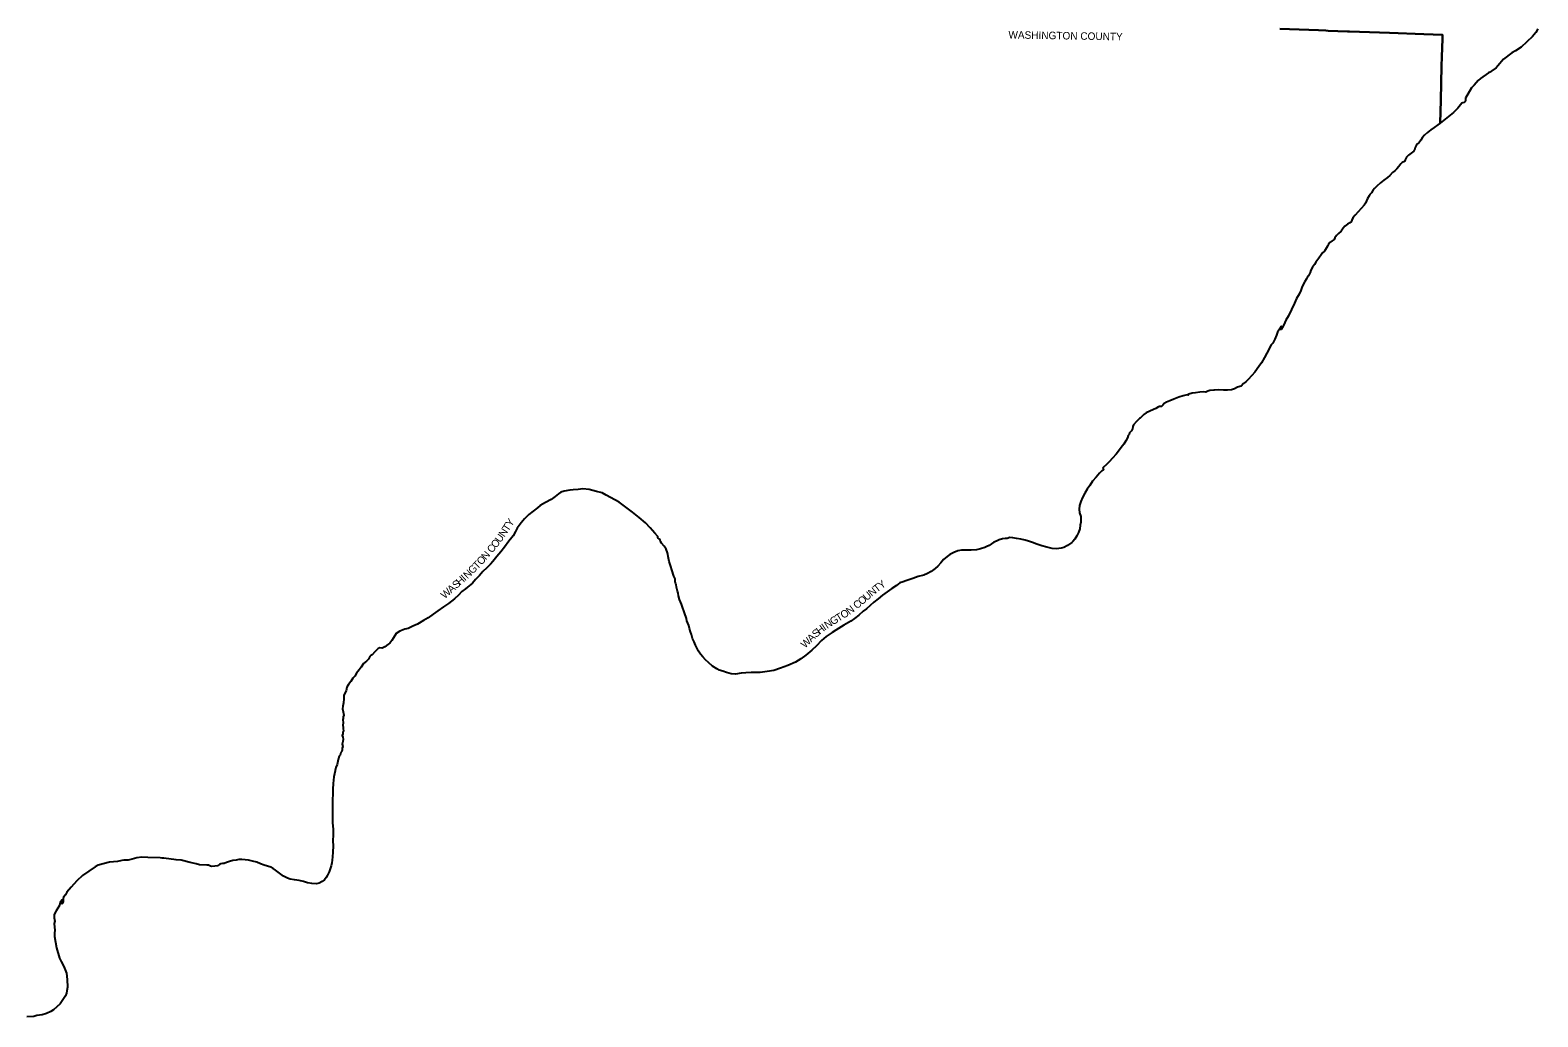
# Model space of a CAD drawing. Extents: x 2043100 to 2470832, y 443715 to 810583.
# Drawn here: x 2192662 to 2393554, y 445118 to 576519 of the extents above; entities that cross this region are included whole.
import ezdxf

# ---------------------------------------------------------------- set-up
doc = ezdxf.new("R2010")
doc.units = 0
doc.layers.add('GM_X_Adjacent_County', color=7, linetype='Continuous')
doc.layers.add('GM_X_Adjacent_County_Text', color=7, linetype='Continuous')

msp = doc.modelspace()

# ---------------------------------------------------------------- linework, layer by layer
at = {"layer": 'GM_X_Adjacent_County'}
for points in [[(2359185, 576678), (2364316, 576498), (2365308, 576463), (2365624, 576452), (2368204, 576361), (2368448, 576353), (2373769, 576167), (2378345, 576006), (2380854, 575918), (2380838, 575354), (2380769, 572951), (2380735, 571740), (2380605, 567204), (2380518, 564153), (2380206, 563892), (2379758, 563556), (2379288, 563234), (2378848, 562883), (2378470, 562536), (2378155, 562185), (2377945, 561869), (2377755, 561577), (2377505, 561385), (2377336, 561168), (2377212, 560895), (2377115, 560525), (2377027, 560393), (2376654, 560121), (2376323, 559858), (2376068, 559619), (2375885, 559250), (2375782, 559024), (2375479, 558909), (2375289, 558727), (2375028, 558347), (2374766, 558062), (2374493, 557793), (2374165, 557570), (2373843, 557168), (2373530, 556895), (2373042, 556563), (2372604, 556201), (2372102, 555735), (2371767, 555419), (2371585, 555176), (2371371, 554852), (2371178, 554644), (2371088, 554460), (2370837, 554120), (2370569, 553501), (2370393, 553211), (2369999, 552760), (2369610, 552327), (2369210, 551890), (2368917, 551519), (2368761, 551212), (2368686, 550992), (2368522, 550842), (2368192, 550662), (2367843, 550404), (2367622, 550168), (2367327, 549761), (2366995, 549445), (2366741, 549162), (2366506, 548866), (2366395, 548652), (2366135, 548480), (2365854, 548249), (2365642, 548032), (2365536, 547748), (2365134, 547107), (2364877, 546854), (2364696, 546593), (2364360, 546141), (2363968, 545629), (2363804, 545330), (2363535, 544941), (2363322, 544577), (2363228, 544253), (2363123, 544059), (2363006, 543787), (2362807, 543586), (2362717, 543406), (2362498, 543056), (2362146, 542376), (2361975, 541860), (2361734, 541352), (2361415, 540780), (2361115, 540184), (2360315, 538483), (2359971, 537881), (2359689, 537272), (2359486, 536874), (2359335, 536647), (2359273, 536653), (2359306, 536837), (2359382, 537043), (2359347, 537046), (2359208, 536848), (2358867, 536280), (2358724, 535921), (2358497, 535373), (2358222, 534848), (2358019, 534604), (2357455, 533512), (2357145, 532912), (2356738, 532231), (2356377, 531721), (2355846, 530970), (2355433, 530532), (2354970, 530004), (2354659, 529665), (2354350, 529463), (2354041, 529120), (2353556, 528965), (2353151, 528748), (2352753, 528626), (2352208, 528569), (2351661, 528569), (2350972, 528598), (2350479, 528585), (2350400, 528583), (2349862, 528548), (2349583, 528421), (2349313, 528313), (2348975, 528369), (2348537, 528331), (2347940, 528220), (2347503, 528156), (2347041, 528032), (2346952, 527931), (2346811, 527945), (2346309, 527818), (2345704, 527644), (2345063, 527390), (2344527, 527134), (2344075, 526994), (2343750, 526810), (2343566, 526563), (2343397, 526414), (2343163, 526415), (2342991, 526351), (2342666, 526142), (2342340, 525992), (2341853, 525795), (2341351, 525570), (2341049, 525346), (2340734, 525003), (2340546, 524863), (2340463, 524801), (2340068, 524423), (2339684, 523960), (2339602, 523729), (2339555, 523445), (2339408, 523168), (2339147, 522882), (2339085, 522675), (2338980, 522553), (2338875, 522239), (2338667, 521831), (2338370, 521374), (2338022, 520920), (2337680, 520450), (2337345, 520055), (2336894, 519540), (2336444, 519041), (2336061, 518661), (2335630, 518270), (2335611, 518186), (2335668, 518090), (2335642, 517973), (2335459, 517843), (2335167, 517536), (2334720, 516997), (2334233, 516435), (2333838, 515901), (2333500, 515393), (2333210, 514860), (2332875, 514302), (2332647, 513749), (2332473, 513195), (2332429, 512723), (2332495, 512255), (2332638, 511741), (2332655, 510988), (2332590, 510576), (2332541, 510102), (2332358, 509624), (2332127, 509182), (2331841, 508713), (2331602, 508406), (2331455, 508309), (2330863, 507893), (2330384, 507638), (2330030, 507541), (2329425, 507441), (2328832, 507500), (2328123, 507666), (2327474, 507837), (2326813, 508075), (2326238, 508285), (2325695, 508473), (2325222, 508593), (2324670, 508715), (2324100, 508826), (2323589, 508916), (2323215, 508939), (2322845, 508833), (2322572, 508841), (2322229, 508775), (2321769, 508622), (2321440, 508478), (2321065, 508329), (2320764, 508110), (2320444, 507909), (2320135, 507772), (2319874, 507626), (2319311, 507457), (2318746, 507330), (2318043, 507272), (2317315, 507264), (2316756, 507274), (2316268, 507188), (2315742, 506970), (2315218, 506698), (2314827, 506431), (2314358, 506010), (2313985, 505587), (2313600, 505142), (2313254, 504843), (2312699, 504415), (2312237, 504148), (2311723, 503952), (2310978, 503755), (2310274, 503508), (2309330, 503196), (2308967, 503072), (2308524, 502898), (2308078, 502547), (2307489, 502168), (2306856, 501732), (2306237, 501272), (2305654, 500793), (2305073, 500323), (2304576, 499879), (2304111, 499448), (2303675, 499131), (2303064, 498607), (2302491, 498180), (2301995, 497820), (2301376, 497477), (2301082, 497264), (2300722, 497072), (2300023, 496611), (2299524, 496324), (2298725, 495767), (2298099, 495219), (2297431, 494533), (2296800, 493953), (2296025, 493278), (2295345, 492775), (2294655, 492372), (2293617, 491910), (2292655, 491546), (2291769, 491263), (2290855, 491114), (2289954, 490997), (2289559, 490973), (2289341, 490960), (2288715, 490966), (2288016, 490944), (2287383, 490875), (2286660, 490773), (2286056, 490817), (2285464, 490960), (2284954, 491136), (2284481, 491291), (2284164, 491450), (2283576, 491824), (2283033, 492289), (2282659, 492669), (2282308, 493064), (2282001, 493427), (2281709, 493831), (2281489, 494244), (2281297, 494604), (2281121, 495045), (2280921, 495490), (2280783, 496014), (2280636, 496385), (2280536, 496855), (2280445, 497253), (2280298, 497542), (2280170, 497855), (2280120, 498186), (2280048, 498454), (2279925, 498667), (2279466, 500083), (2279204, 500711), (2279052, 501183), (2278991, 501521), (2278930, 501793), (2278781, 502329), (2278744, 502688), (2278661, 502876), (2278586, 503111), (2278615, 503433), (2278431, 503803), (2278369, 503938), (2278186, 504513), (2277983, 505206), (2277802, 505761), (2277702, 506219), (2277589, 506900), (2277426, 507395), (2277151, 507806), (2276777, 508205), (2276649, 508405), (2276618, 508581), (2276529, 508718), (2276309, 508901), (2276280, 509075), (2275910, 509542), (2275255, 510256), (2274636, 510903), (2273828, 511604), (2272919, 512325), (2272197, 512856), (2271126, 513670), (2270589, 513992), (2269398, 514614), (2268891, 514898), (2268137, 515102), (2267168, 515352), (2266312, 515423), (2265671, 515365), (2265009, 515320), (2264563, 515262), (2263811, 515125), (2263356, 514994), (2263070, 514786), (2262636, 514413), (2262095, 514016), (2261334, 513617), (2260616, 513223), (2260245, 512907), (2259694, 512482), (2259107, 512000), (2258521, 511447), (2258074, 510887), (2257566, 510198), (2257338, 509734), (2257013, 509158), (2256854, 508971), (2256429, 508462), (2255864, 507670), (2255387, 507057), (2254857, 506411), (2254319, 505772), (2253982, 505392), (2253507, 504928), (2253001, 504419), (2252542, 503905), (2252006, 503353), (2251583, 502884), (2251177, 502528), (2250955, 502356), (2250684, 502138), (2250188, 501741), (2249741, 501262), (2249195, 500794), (2248393, 500170), (2247748, 499699), (2246994, 499182), (2246371, 498723), (2245716, 498276), (2245080, 497887), (2244288, 497429), (2243667, 497133), (2243040, 496830), (2242588, 496730), (2241930, 496473), (2241433, 496184), (2241096, 495614), (2240859, 495254), (2240569, 494878), (2240337, 494684), (2239912, 494384), (2239556, 494195), (2239243, 494275), (2239039, 494178), (2238608, 493740), (2238229, 493334), (2238064, 493258), (2237908, 493090), (2237742, 492737), (2237477, 492483), (2237076, 492185), (2236746, 491696), (2236496, 491330), (2236139, 490896), (2235908, 490496), (2235666, 490202), (2235373, 489758), (2235077, 489371), (2234872, 489002), (2234776, 488541), (2234599, 488234), (2234451, 487906), (2234460, 487477), (2234409, 486927), (2234316, 486487), (2234292, 486124), (2234360, 485720), (2234442, 485282), (2234378, 485063), (2234375, 484846), (2234303, 484701), (2234363, 484251), (2234340, 483978), (2234376, 483668), (2234349, 483453), (2234400, 483225), (2234338, 483046), (2234345, 482828), (2234258, 482570), (2234303, 482346), (2234375, 482112), (2234314, 481805), (2234255, 481449), (2234319, 481134), (2234258, 480908), (2234243, 480690), (2234174, 480450), (2234079, 480299), (2233964, 479955), (2233853, 479821), (2233711, 479382), (2233559, 478729), (2233394, 478316), (2233305, 477906), (2233295, 477864), (2233143, 477090), (2233029, 476171), (2232988, 475460), (2232976, 474703), (2232945, 474139), (2232932, 473117), (2232928, 471946), (2232956, 471018), (2233026, 470053), (2233049, 469368), (2233004, 468537), (2233031, 467894), (2232992, 467062), (2232964, 466440), (2232924, 465981), (2232848, 465645), (2232757, 465239), (2232618, 464850), (2232496, 464420), (2232277, 463974), (2232115, 463663), (2231898, 463370), (2231549, 463121), (2231193, 462926), (2230828, 462831), (2230216, 462871), (2229628, 462984), (2229095, 463122), (2228506, 463294), (2227875, 463385), (2227313, 463474), (2226945, 463579), (2226400, 463853), (2226069, 464105), (2225716, 464381), (2225344, 464629), (2225021, 464861), (2224744, 465036), (2224291, 465175), (2223855, 465303), (2223369, 465513), (2222868, 465697), (2222273, 465870), (2221748, 465982), (2221299, 466030), (2220876, 466054), (2220473, 466057), (2220111, 466004), (2219669, 465921), (2219222, 465801), (2218821, 465659), (2218496, 465551), (2218276, 465534), (2218050, 465509), (2217889, 465418), (2217626, 465249), (2217285, 465168), (2216888, 465155), (2216673, 465184), (2216430, 465295), (2216198, 465304), (2215240, 465376), (2214796, 465508), (2213975, 465680), (2212780, 465966), (2212123, 466022), (2210454, 466256), (2210241, 466256), (2209964, 466298), (2208339, 466328), (2207555, 466366), (2206893, 466287), (2206267, 466125), (2205718, 465991), (2205129, 465973), (2204877, 465917), (2204284, 465787), (2203232, 465703), (2201705, 465321), (2201323, 465085), (2199637, 463932), (2198884, 463234), (2198109, 462370), (2197545, 461700), (2197379, 461376), (2197121, 461072), (2197063, 460812), (2197077, 460472), (2197018, 460253), (2196910, 460173), (2196862, 460273), (2196996, 460704), (2196866, 460670), (2196650, 460356), (2196606, 460147), (2196588, 459931), (2196109, 459243), (2195960, 458937), (2195870, 458695), (2195852, 458287), (2195944, 457861), (2195874, 457528), (2195938, 456594), (2195910, 456287), (2195926, 455813), (2196160, 454320), (2196587, 452932), (2196801, 452484), (2197163, 451801), (2197505, 450948), (2197590, 450073), (2197633, 449049), (2197563, 448576), (2197507, 448251), (2197381, 447899), (2196657, 446862), (2195755, 446040), (2195435, 445827), (2194859, 445549), (2194241, 445400), (2193535, 445295), (2193163, 445166), (2192204, 445118)], [(2393554, 576695), (2393303, 576189), (2392830, 575658), (2391342, 574266), (2390568, 573752), (2390076, 573483), (2388984, 572651), (2388238, 571748), (2387984, 571507), (2387410, 571098), (2387278, 570966), (2386970, 570843), (2385901, 570061), (2385621, 569802), (2385087, 569200), (2384731, 568839), (2383929, 567456), (2383909, 567157), (2383831, 566963), (2383729, 566878), (2383537, 566862), (2383429, 566802), (2382907, 566124), (2382322, 565569), (2380518, 564153), (2380605, 567204), (2380735, 571740), (2380769, 572951), (2380838, 575354), (2380854, 575918), (2378345, 576006), (2373769, 576167), (2368448, 576353), (2368204, 576361), (2365624, 576452), (2365308, 576463), (2364316, 576498), (2359185, 576678)]]:
    msp.add_lwpolyline(points, dxfattribs=at)

# ---------------------------------------------------------------- texts
at = {"layer": 'GM_X_Adjacent_County_Text'}
for s, rotation, p in [('WASHINGTON COUNTY', 359.00556, (2323005, 575416)), ('T', 56.75848, (2256345, 509682)), ('Y', 54.87573, (2256750, 510301)), ('O', 51.07917, (2254724, 507449)), ('U', 54.40982, (2255318, 508188)), ('N', 56.62653, (2255857, 508942)), ('O', 46.89254, (2252779, 505211)), ('N', 49.21658, (2253413, 505890)), ('C', 50.52237, (2254200, 506812)), ('N', 42.82871, (2250929, 503393)), ('G', 44.96605, (2251607, 504023)), ('T', 45.89283, (2252245, 504660)), ('W', 41.33683, (2247901, 500724)), ('A', 41.3364, (2248766, 501485)), ('S', 41.3373, (2249430, 502070)), ('H', 41.37797, (2249940, 502518)), ('I', 41.73275, (2250608, 503107)), ('N', 39.3127, (2304809, 501035)), ('T', 37.85245, (2305488, 501591)), ('Y', 36.40274, (2306073, 502046)), ('C', 39.64325, (2302824, 499376)), ('O', 40.01875, (2303457, 499900)), ('U', 40.00751, (2304134, 500468)), ('G', 31.90891, (2299609, 497245)), ('T', 31.59939, (2300358, 497711)), ('O', 31.20404, (2300994, 498102)), ('N', 36.8578, (2301840, 498621)), ('S', 42.47696, (2297379, 495550)), ('H', 38.70638, (2297866, 495996)), ('I', 34.81161, (2298541, 496538)), ('N', 32.89249, (2298870, 496767)), ('W', 43.53839, (2295904, 494152)), ('A', 43.36836, (2296739, 494945))]:
    msp.add_text(s, height=1000, rotation=rotation, dxfattribs=at).set_placement(p)

doc.saveas('drawing.dxf')
